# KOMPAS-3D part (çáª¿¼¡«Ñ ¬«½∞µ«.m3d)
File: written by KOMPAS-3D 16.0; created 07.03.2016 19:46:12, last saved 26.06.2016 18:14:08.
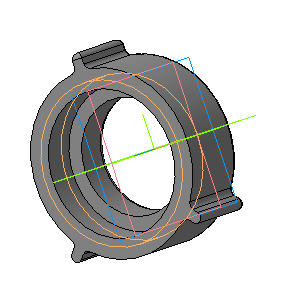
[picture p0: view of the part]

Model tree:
1. Эскиз:1
2. Операция выдавливания:2
     Толщина стенки 1 = 11; Расстояние 1 = 25
3. Эскиз:2
4. Скругление:1
     Радиус = 2
5. Эскиз:3
6. Вырезать элемент выдавливания:2
     Расстояние 1 = 30
7. Скругление:2
     Радиус = 2
8. Скругление:3
     Радиус = 1
9. Вырезать элемент выдавливания:3
     Расстояние 1 = 12
10. Условное изображение резьбы:2  (labels: E:\Sys\Thread\cil0_8724-2002 coarse.xml; M56)
     Длина резьбы = 12; Шаг резьбы = 5.5; Номинальный диаметр резьбы = 56
11. Подгонка:1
